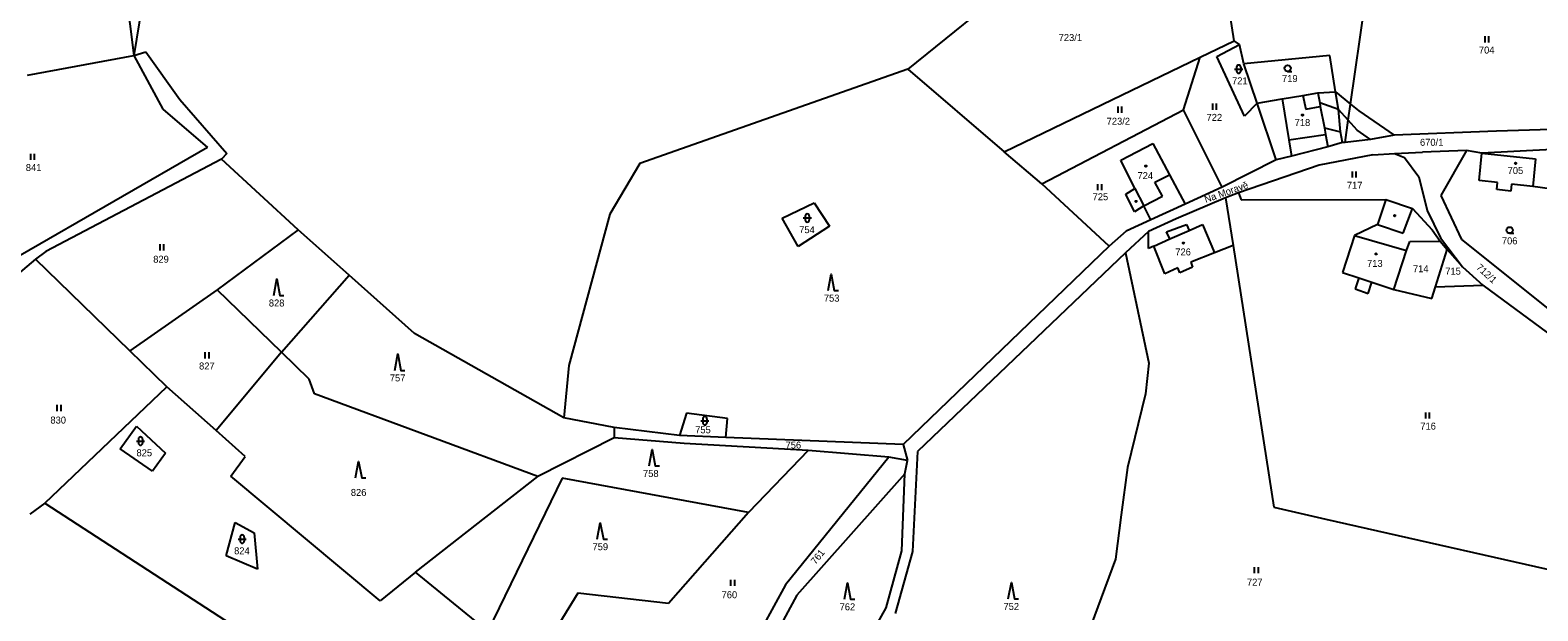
# Model space of a CAD drawing. Extents: x -670359 to -668019, y -978807 to -976674.
# Drawn here: x -669008.2 to -668641.1, y -977788.7 to -977647.3 of the extents above; entities that cross this region are included whole.
import ezdxf

# ---------------------------------------------------------------- set-up
doc = ezdxf.new("R2010")
doc.units = 0
for name, color, linetype in [('Hranice parcel', 7, 'Continuous'), ('Parcelní čísla', 7, 'Continuous'), ('Pop  PČ popisy', 7, 'Continuous'), ('Vnitřní kresba', 7, 'Continuous'), ('Značky budov', 7, 'Continuous'), ('Značky kultur', 7, 'Continuous')]:
    doc.layers.add(name, color=color, linetype=linetype)

msp = doc.modelspace()

# ---------------------------------------------------------------- linework, layer by layer
at = {"layer": 'Hranice parcel'}
for p, q in [((-668681.33, -977677.62), (-668676.08, -977677.36)), ((-668676.08, -977677.36), (-668669.23, -977677.01)), ((-668676.08, -977677.36), (-668673.57, -977678.31)), ((-668673.57, -977678.31), (-668670.12, -977683.02)), ((-668670.12, -977683.02), (-668668.13, -977691.22)), ((-668668.13, -977691.22), (-668664.81, -977697.85)), ((-668664.81, -977697.85), (-668659.48, -977704.96)), ((-669004.63, -977762.49), (-668947.9, -977799.28))]:
    msp.add_line(p, q, dxfattribs=at)
for points in [[(-668963.02, -977531.02), (-668982.97, -977653.48)], [(-668989.68, -977600.01), (-668982.97, -977653.48)], [(-668715.1, -977649.92), (-668721.21, -977610.14)], [(-668767.17, -977634.66), (-668794.55, -977656.82)], [(-668686.75, -977665.31), (-668683.29, -977641.13)], [(-668723.36, -977653.9), (-668715.1, -977649.92)], [(-668719.28, -977653.67), (-668713.74, -977650.81)], [(-668713.74, -977650.81), (-668715.1, -977649.92)], [(-668712.72, -977655.53), (-668713.74, -977650.81)], [(-669008.85, -977658.21), (-668982.97, -977653.48)], [(-668982.97, -977653.48), (-668980, -977652.53)], [(-668982.97, -977653.48), (-668975.88, -977666.55)], [(-668980, -977652.53), (-668971.79, -977664.16)], [(-668771.03, -977676.89), (-668723.36, -977653.9)], [(-668727.41, -977666.69), (-668723.36, -977653.9)], [(-668712.6, -977668.25), (-668719.28, -977653.67)], [(-668691.81, -977653.43), (-668712.72, -977655.53)], [(-668690.4, -977662.31), (-668691.81, -977653.43)], [(-668794.55, -977656.82), (-668859.8, -977679.76)], [(-668794.55, -977656.82), (-668771.03, -977676.89)], [(-668709.51, -977665.09), (-668712.72, -977655.53)], [(-668971.79, -977664.16), (-668960.3, -977677.31)], [(-668709.51, -977665.09), (-668712.6, -977668.25)], [(-668709.51, -977665.09), (-668703.38, -977664.04)], [(-668704.87, -977678.91), (-668709.51, -977665.09)], [(-668703.38, -977664.04), (-668698.33, -977663.17)], [(-668698.33, -977663.17), (-668694.72, -977662.55)], [(-668694.72, -977662.55), (-668694.2, -977665)], [(-668694.2, -977665), (-668694.1, -977665.9)], [(-668689.7, -977666.63), (-668690.4, -977662.31)], [(-668687.31, -977669.25), (-668686.75, -977665.31)], [(-668975.88, -977666.55), (-668965.02, -977675.86)], [(-668761.9, -977684.68), (-668727.41, -977666.69)], [(-668718, -977685.5), (-668727.41, -977666.69)], [(-668694.1, -977665.9), (-668693.07, -977671.11)], [(-668689.15, -977672.08), (-668689.7, -977666.63)], [(-668688.08, -977674.64), (-668687.31, -977669.25)], [(-668693.07, -977671.11), (-668692.84, -977672.71)], [(-668692.84, -977672.71), (-668692.28, -977675.71)], [(-668688.7, -977674.64), (-668689.15, -977672.08)], [(-668676.11, -977672.83), (-668681.87, -977673.94)], [(-668651.2, -977671.86), (-668676.11, -977672.83)], [(-668632.55, -977671.35), (-668651.2, -977671.86)], [(-668965.02, -977675.86), (-669010.6, -977702.14)], [(-668742.66, -977678.97), (-668734.88, -977674.91)], [(-668734.88, -977674.91), (-668730.82, -977682.52)], [(-668692.28, -977675.71), (-668701.09, -977677.95)], [(-668688.7, -977674.64), (-668692.28, -977675.71)], [(-668688.08, -977674.64), (-668688.7, -977674.64)], [(-668681.87, -977673.94), (-668688.08, -977674.64)], [(-668658.5, -977676.56), (-668669.23, -977677.01)], [(-668658.5, -977676.56), (-668664.79, -977687.59)], [(-668654.82, -977677.21), (-668658.5, -977676.56)], [(-668637.69, -977676.34), (-668654.82, -977677.21)], [(-668961.59, -977678.67), (-669004.35, -977701.2)], [(-668960.3, -977677.31), (-668961.59, -977678.67)], [(-668942.91, -977695.93), (-668961.59, -977678.67)], [(-668859.8, -977679.76), (-668867.05, -977692.07)], [(-668761.9, -977684.68), (-668771.03, -977676.89)], [(-668739.24, -977685.86), (-668742.66, -977678.97)], [(-668704.87, -977678.91), (-668718, -977685.5)], [(-668694.39, -977680.14), (-668714.02, -977686.89)], [(-668701.09, -977677.95), (-668704.87, -977678.91)], [(-668681.33, -977677.62), (-668694.39, -977680.14)], [(-668655.41, -977683.93), (-668654.82, -977677.21)], [(-668730.82, -977682.52), (-668727.02, -977689.65)], [(-668650.99, -977684.4), (-668655.41, -977683.93)], [(-668745.53, -977699.92), (-668761.9, -977684.68)], [(-668741.49, -977687.21), (-668739.24, -977685.86)], [(-668739.34, -977691.54), (-668741.49, -977687.21)], [(-668718, -977685.5), (-668727.02, -977689.65)], [(-668714.02, -977686.89), (-668717.15, -977688.16)], [(-668714.02, -977686.89), (-668713.39, -977688.65)], [(-668664.79, -977687.59), (-668659.7, -977698.24)], [(-668651.17, -977686.1), (-668650.99, -977684.4)], [(-668647.73, -977686.51), (-668651.17, -977686.1)], [(-668647.54, -977684.77), (-668647.73, -977686.51)], [(-668642.36, -977685.33), (-668647.54, -977684.77)], [(-668638.2, -977685.9), (-668642.36, -977685.33)], [(-668825.1, -977693.06), (-668817.32, -977689.32)], [(-668817.32, -977689.32), (-668813.57, -977695.01)], [(-668737.09, -977690.11), (-668739.34, -977691.54)], [(-668735.39, -977693.5), (-668737.09, -977690.11)], [(-668727.02, -977689.65), (-668735.39, -977693.5)], [(-668717.15, -977688.16), (-668729.18, -977693.25)], [(-668717.15, -977688.16), (-668715.35, -977699.72)], [(-668713.39, -977688.65), (-668678.16, -977688.51)], [(-668678.16, -977688.51), (-668680.18, -977694.66)], [(-668678.16, -977688.51), (-668671.68, -977690.69)], [(-668671.68, -977690.69), (-668666.9, -977695.9)], [(-668867.05, -977692.07), (-668877.02, -977728.92)], [(-668821.2, -977699.95), (-668825.1, -977693.06)], [(-668813.57, -977695.01), (-668821.2, -977699.95)], [(-668735.39, -977693.5), (-668741.36, -977696.25)], [(-668729.18, -977693.25), (-668735.91, -977696.35)], [(-668680.18, -977694.66), (-668685.8, -977697.29)], [(-668942.91, -977695.93), (-668962.66, -977710.52)], [(-668930.53, -977706.93), (-668942.91, -977695.93)], [(-668741.36, -977696.25), (-668745.53, -977699.92)], [(-668735.91, -977696.35), (-668741.54, -977701.53)], [(-668735.93, -977700.43), (-668735.91, -977696.35)], [(-668685.8, -977697.29), (-668688.71, -977706.32)], [(-668672.27, -977698.77), (-668664.9, -977698.71)], [(-668666.9, -977695.9), (-668664.9, -977698.71)], [(-668664.9, -977698.71), (-668663.23, -977700.71)], [(-668659.7, -977698.24), (-668638.3, -977715.42)], [(-669004.35, -977701.2), (-669006.92, -977703.03)], [(-668745.53, -977699.92), (-668795.66, -977748.19)], [(-668741.54, -977701.53), (-668792.14, -977749.88)], [(-668741.54, -977701.53), (-668735.86, -977728.43)], [(-668734.65, -977699.87), (-668735.93, -977700.43)], [(-668731.95, -977706.6), (-668734.65, -977699.87)], [(-668719.84, -977701.51), (-668725.61, -977703.82)], [(-668715.35, -977699.72), (-668719.84, -977701.51)], [(-668715.35, -977699.72), (-668705.39, -977763.48)], [(-668676.23, -977710.44), (-668673.16, -977700.92)], [(-668673.16, -977700.92), (-668672.27, -977698.77)], [(-668666.06, -977709.82), (-668663.23, -977700.71)], [(-668663.23, -977700.71), (-668659.48, -977704.96)], [(-669006.92, -977703.03), (-669015.35, -977710.21)], [(-668983.93, -977725.42), (-669006.92, -977703.03)], [(-668728.82, -977705.17), (-668731.95, -977706.6)], [(-668728.34, -977706.37), (-668728.82, -977705.17)], [(-668725.21, -977705.02), (-668728.34, -977706.37)], [(-668725.61, -977703.82), (-668725.21, -977705.02)], [(-668659.48, -977704.96), (-668654.53, -977709.38)], [(-668947.01, -977725.69), (-668930.53, -977706.93)], [(-668914.63, -977721.14), (-668930.53, -977706.93)], [(-668688.71, -977706.32), (-668684.74, -977707.63)], [(-668684.74, -977707.63), (-668685.6, -977710.25)], [(-668682.48, -977711.46), (-668681.56, -977708.68)], [(-668681.56, -977708.68), (-668676.23, -977710.44)], [(-668666.06, -977709.82), (-668654.53, -977709.38)], [(-668654.53, -977709.38), (-668634.16, -977724.39)], [(-668962.66, -977710.52), (-668983.93, -977725.42)], [(-668947.01, -977725.69), (-668962.66, -977710.52)], [(-668685.6, -977710.25), (-668682.48, -977711.46)], [(-668676.23, -977710.44), (-668666.95, -977712.62)], [(-668666.95, -977712.62), (-668666.06, -977709.82)], [(-668878.26, -977741.72), (-668914.63, -977721.14)], [(-668974.91, -977734.17), (-668983.93, -977725.42)], [(-668947.01, -977725.69), (-668962.93, -977744.77)], [(-668940.23, -977732.27), (-668947.01, -977725.69)], [(-668877.02, -977728.92), (-668878.26, -977741.72)], [(-668735.86, -977728.43), (-668736.68, -977735.84)], [(-669004.63, -977762.49), (-668974.91, -977734.17)], [(-668962.93, -977744.77), (-668974.91, -977734.17)], [(-668938.96, -977735.87), (-668940.23, -977732.27)], [(-668884.57, -977756.03), (-668938.96, -977735.87)], [(-668736.68, -977735.84), (-668741.01, -977753.81)], [(-668866.02, -977744.07), (-668878.26, -977741.72)], [(-668848.4, -977740.6), (-668850.1, -977746.04)], [(-668838.39, -977741.83), (-668848.4, -977740.6)], [(-668838.81, -977746.47), (-668838.39, -977741.83)], [(-668986.25, -977749.26), (-668982.31, -977743.75)], [(-668982.31, -977743.75), (-668975.28, -977750.33)], [(-668955.82, -977751.11), (-668962.93, -977744.77)], [(-668866.02, -977744.07), (-668866.03, -977746.55)], [(-668850.1, -977746.04), (-668866.02, -977744.07)], [(-668838.81, -977746.47), (-668850.1, -977746.04)], [(-668978.42, -977754.73), (-668986.25, -977749.26)], [(-668866.03, -977746.55), (-668884.57, -977756.03)], [(-668848.98, -977747.96), (-668866.03, -977746.55)], [(-668818.8, -977749.64), (-668848.98, -977747.96)], [(-668795.66, -977748.19), (-668838.81, -977746.47)], [(-668818.8, -977749.64), (-668833.34, -977764.73)], [(-668799.11, -977751.3), (-668818.8, -977749.64)], [(-668795.66, -977748.19), (-668794.63, -977752.11)], [(-668792.14, -977749.88), (-668793.42, -977774.28)], [(-668975.28, -977750.33), (-668978.42, -977754.73)], [(-668959.36, -977755.9), (-668955.82, -977751.11)], [(-668799.11, -977751.3), (-668824.28, -977782.35)], [(-668794.63, -977752.11), (-668799.11, -977751.3)], [(-668795.28, -977755.31), (-668794.63, -977752.11)], [(-668922.95, -977786.25), (-668959.36, -977755.9)], [(-668914.35, -977779.31), (-668884.57, -977756.03)], [(-668878.71, -977756.36), (-668896.77, -977793.67)], [(-668833.34, -977764.73), (-668878.71, -977756.36)], [(-668795.28, -977755.31), (-668821.56, -977784.92)], [(-668795.99, -977774.11), (-668795.28, -977755.31)], [(-668741.01, -977753.81), (-668742.62, -977765.36)], [(-669004.63, -977762.49), (-669008.24, -977765.2)], [(-668833.34, -977764.73), (-668852.8, -977786.91)], [(-668705.39, -977763.48), (-668692.75, -977766.4)], [(-668960.47, -977775.34), (-668958.28, -977767.19)], [(-668958.28, -977767.19), (-668953.64, -977769.68)], [(-668742.62, -977765.36), (-668743.95, -977776.09)], [(-668692.75, -977766.4), (-668626.59, -977781.3)], [(-668953.64, -977769.68), (-668952.87, -977778.56)], [(-668952.87, -977778.56), (-668960.47, -977775.34)], [(-668799.8, -977788.02), (-668795.99, -977774.11)], [(-668793.42, -977774.28), (-668797.64, -977789.39)], [(-668914.35, -977779.31), (-668922.95, -977786.25)], [(-668896.77, -977793.67), (-668914.35, -977779.31)], [(-668743.95, -977776.09), (-668756.86, -977810.95)], [(-668824.28, -977782.35), (-668830, -977792.74)], [(-668874.89, -977784.37), (-668882.94, -977797.63)], [(-668852.8, -977786.91), (-668874.89, -977784.37)], [(-668821.56, -977784.92), (-668826.48, -977794.03)], [(-668805.92, -977798.89), (-668799.8, -977788.02)]]:
    msp.add_lwpolyline(points, dxfattribs=at)
at = {"layer": 'Vnitřní kresba'}
for points in [[(-668703.38, -977664.04), (-668701.73, -977674.04)], [(-668698.33, -977663.17), (-668697.62, -977666.53)], [(-668694.72, -977662.55), (-668690.4, -977662.31)], [(-668689.7, -977666.63), (-668694.2, -977665)], [(-668690.4, -977662.31), (-668686.75, -977665.31)], [(-668686.75, -977665.31), (-668684.73, -977666.97)], [(-668697.62, -977666.53), (-668694.1, -977665.9)], [(-668687.31, -977669.25), (-668689.7, -977666.63)], [(-668685.15, -977671.61), (-668687.31, -977669.25)], [(-668684.73, -977666.97), (-668676.11, -977672.83)], [(-668701.73, -977674.04), (-668692.84, -977672.71)], [(-668693.07, -977671.11), (-668689.15, -977672.08)], [(-668681.87, -977673.94), (-668685.15, -977671.61)], [(-668701.73, -977674.04), (-668701.09, -977677.95)], [(-668654.82, -977677.21), (-668641.7, -977678.61)], [(-668641.7, -977678.61), (-668642.36, -977685.33)], [(-668734.35, -977684.27), (-668730.82, -977682.52)], [(-668739.24, -977685.86), (-668737.09, -977690.11)], [(-668737.09, -977690.11), (-668732.52, -977687.72)], [(-668732.52, -977687.72), (-668734.35, -977684.27)], [(-668673.94, -977696.76), (-668671.68, -977690.69)], [(-668731.51, -977696.44), (-668726.7, -977694.61)], [(-668726.7, -977694.61), (-668726.05, -977696.07)], [(-668726.05, -977696.07), (-668722.78, -977694.63)], [(-668722.78, -977694.63), (-668719.84, -977701.51)], [(-668680.18, -977694.66), (-668673.94, -977696.76)], [(-668734.65, -977699.87), (-668730.75, -977698.15)], [(-668730.75, -977698.15), (-668731.51, -977696.44)], [(-668730.75, -977698.15), (-668726.05, -977696.07)], [(-668685.8, -977697.29), (-668673.16, -977700.92)], [(-668684.74, -977707.63), (-668681.56, -977708.68)]]:
    msp.add_lwpolyline(points, dxfattribs=at)
at = {"layer": 'Značky budov'}
for centre in [(-668698.44, -977667.98), (-668736.58, -977680.41), (-668646.57, -977679.73), (-668727.42, -977699.14), (-668680.53, -977701.79)]:
    msp.add_circle(centre, 0.175, dxfattribs=at)
at = {"layer": 'Značky kultur'}
for p, q in [((-668654.04, -977648.78), (-668654.04, -977650.28)), ((-668653.04, -977650.28), (-668653.04, -977648.78)), ((-668714.98, -977656.78), (-668712.98, -977656.78)), ((-668714.48, -977656.28), (-668714.48, -977657.28)), ((-668713.48, -977656.28), (-668713.48, -977657.28)), ((-668702.06, -977657.33), (-668701.06, -977657.33)), ((-668720.37, -977665.18), (-668720.37, -977666.68)), ((-668719.37, -977666.68), (-668719.37, -977665.18)), ((-668743.41, -977665.92), (-668743.41, -977667.42)), ((-668742.41, -977667.42), (-668742.41, -977665.92)), ((-669008.14, -977677.41), (-669008.14, -977678.91)), ((-669007.14, -977678.91), (-669007.14, -977677.41)), ((-668686.35, -977681.71), (-668686.35, -977683.21)), ((-668685.35, -977683.21), (-668685.35, -977681.71)), ((-668748.31, -977684.78), (-668748.31, -977686.28)), ((-668747.31, -977686.28), (-668747.31, -977684.78)), ((-668820.01, -977693.03), (-668818.01, -977693.03)), ((-668819.51, -977692.53), (-668819.51, -977693.53)), ((-668818.51, -977692.53), (-668818.51, -977693.53)), ((-668648.01, -977696.75), (-668647.01, -977696.75)), ((-668976.63, -977699.42), (-668976.63, -977700.92)), ((-668975.63, -977700.92), (-668975.63, -977699.42)), ((-668965.64, -977725.73), (-668965.64, -977727.23)), ((-668964.64, -977727.23), (-668964.64, -977725.73)), ((-669001.67, -977738.58), (-669001.67, -977740.08)), ((-669000.67, -977740.08), (-669000.67, -977738.58)), ((-668844.93, -977742.41), (-668842.93, -977742.41)), ((-668844.43, -977741.91), (-668844.43, -977742.91)), ((-668843.43, -977741.91), (-668843.43, -977742.91)), ((-668668.51, -977740.37), (-668668.51, -977741.87)), ((-668667.51, -977741.87), (-668667.51, -977740.37)), ((-668982.33, -977747.37), (-668980.33, -977747.37)), ((-668981.83, -977746.87), (-668981.83, -977747.87)), ((-668980.83, -977746.87), (-668980.83, -977747.87)), ((-668957.58, -977771.24), (-668955.58, -977771.24)), ((-668957.08, -977770.74), (-668957.08, -977771.74)), ((-668956.08, -977770.74), (-668956.08, -977771.74)), ((-668710.18, -977778.07), (-668710.18, -977779.57)), ((-668709.18, -977779.57), (-668709.18, -977778.07)), ((-668837.67, -977781.15), (-668837.67, -977782.65)), ((-668836.67, -977782.65), (-668836.67, -977781.15))]:
    msp.add_line(p, q, dxfattribs=at)
for points in [[(-668948.9, -977711.89), (-668948.15, -977707.89), (-668947.4, -977711.89), (-668946.4, -977711.89)], [(-668813.94, -977710.71), (-668813.19, -977706.71), (-668812.44, -977710.71), (-668811.44, -977710.71)], [(-668919.45, -977730.14), (-668918.7, -977726.14), (-668917.95, -977730.14), (-668916.95, -977730.14)], [(-668857.5, -977753.4), (-668856.75, -977749.4), (-668856, -977753.4), (-668855, -977753.4)], [(-668928.97, -977756.33), (-668928.22, -977752.33), (-668927.47, -977756.33), (-668926.47, -977756.33)], [(-668870.14, -977771.24), (-668869.39, -977767.24), (-668868.64, -977771.24), (-668867.64, -977771.24)], [(-668809.95, -977785.89), (-668809.2, -977781.89), (-668808.45, -977785.89), (-668807.45, -977785.89)], [(-668770.06, -977785.8), (-668769.31, -977781.8), (-668768.56, -977785.8), (-668767.56, -977785.8)]]:
    msp.add_lwpolyline(points, dxfattribs=at)
for centre, radius in [((-668702.06, -977656.58), 0.75), ((-668698.44, -977667.98), 0.175), ((-668736.58, -977680.41), 0.175), ((-668646.57, -977679.73), 0.175), ((-668738.95, -977689.01), 0.175), ((-668675.98, -977692.48), 0.175), ((-668648.01, -977696), 0.75), ((-668727.42, -977699.14), 0.175), ((-668680.53, -977701.79), 0.175)]:
    msp.add_circle(centre, radius, dxfattribs=at)
for centre, start, end in [((-668713.98, -977656.28), 0, 180), ((-668713.98, -977657.28), 180, 0), ((-668819.01, -977692.53), 0, 180), ((-668819.01, -977693.53), 180, 0), ((-668843.93, -977741.91), 0, 180), ((-668981.33, -977746.87), 0, 180), ((-668843.93, -977742.91), 180, 0), ((-668981.33, -977747.87), 180, 0), ((-668956.58, -977770.74), 0, 180), ((-668956.58, -977771.74), 180, 0)]:
    msp.add_arc(centre, 0.5, start, end, dxfattribs=at)

# ---------------------------------------------------------------- texts
at = {"layer": 'Parcelní čísla'}
for s, p in [('723/1', (-668757.8, -977649.94)), ('704', (-668655.5, -977652.98)), ('719', (-668703.43, -977659.92)), ('721', (-668715.59, -977660.48)), ('723/2', (-668746.12, -977670.32)), ('722', (-668721.8, -977669.38)), ('718', (-668700.35, -977670.64)), ('670/1', (-668669.84, -977675.45)), ('841', (-669009.25, -977681.61)), ('724', (-668738.61, -977683.57)), ('705', (-668648.5, -977682.33)), ('725', (-668749.54, -977688.71)), ('717', (-668687.64, -977685.91)), ('754', (-668820.97, -977696.73)), ('706', (-668649.9, -977699.45)), ('829', (-668978.23, -977703.93)), ('726', (-668729.4, -977702.15)), ('713', (-668682.72, -977704.95)), ('714', (-668671.55, -977706.25)), ('715', (-668663.68, -977706.84)), ('828', (-668950.08, -977714.59)), ('753', (-668814.96, -977713.41)), ('827', (-668967.07, -977729.93)), ('757', (-668920.63, -977732.84)), ('830', (-669003.26, -977743.1)), ('755', (-668846.29, -977745.47)), ('716', (-668669.76, -977744.57)), ('825', (-668982.3, -977751.07)), ('756', (-668824.29, -977749.18)), ('758', (-668858.99, -977756.11)), ('826', (-668930.12, -977760.72)), ('824', (-668958.54, -977774.94)), ('759', (-668871.28, -977773.94)), ('727', (-668711.96, -977782.57)), ('760', (-668839.86, -977785.64)), ('752', (-668771.24, -977788.5)), ('762', (-668811.13, -977788.59))]:
    msp.add_text(s, height=1.7, dxfattribs=at).set_placement(p)
for s, rotation, p in [('712/1', 317.6264, (-668656.28, -977705.29)), ('761', 51.618, (-668816.98, -977777.55))]:
    msp.add_text(s, height=1.7, rotation=rotation, dxfattribs=at).set_placement(p)
at = {"layer": 'Pop  PČ popisy'}
msp.add_text('Na Moravě', height=1.7, rotation=19.5239, dxfattribs=at).set_placement((-668721.97, -977689.37))

doc.saveas('drawing.dxf')
